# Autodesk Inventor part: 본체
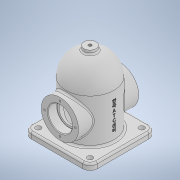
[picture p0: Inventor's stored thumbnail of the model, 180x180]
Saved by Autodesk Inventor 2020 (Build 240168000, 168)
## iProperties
Created: 2021-07
Part Number: 본체
Material: 일반
Document SubType Name: Modeling
Designer: Owner
Density: 1 g/cm^3
Appearance: 기본값
Mass: 320.706 g
Surface Area: 800.755 cm^2
Volume: 320.706 cm^3
Author: Owner
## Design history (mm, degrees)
sketch "스케치1"
  geometry: C1 r 40 at (0, 0); 1 further point
  constraints: 1 centre point, 1 coincident
  dimensions: "d0" = 80 diameter of C1
extrude "돌출1" new body sketch "스케치1" distance "d1" = 124; taper "d2" = 0 deg
fillet "모깎기1" dims "d3" = 40
feature "쉘1" dims "d4" = 8
node "작업 평면1"
sketch "스케치2"
  geometry: C1 r 31 at (0, 48); 1 further point
  constraints: 1 centre point, 1 vertical alignment
  dimensions: "d6" = 62 diameter of C1; "d7" = 48 distance of point (0, 0) C1.centre
extrude "돌출2" join sketch "스케치2" stored distance "d8" = 124; taper "d9" = 0 deg
sketch "스케치3" dims "d10" = 51
  geometry: 3 further points
  constraints: 2 vertical alignment, 2 other
  dimensions: "d11" = 48 distance of point (0, -48) point (0, 0)
hole "구멍1" sketch "스케치3" at (0, 25.5) diameter "d12" = 3.242; stored, may be unused: countersink angle "d16" = 90 deg, drill point angle "d18" = 118 deg; dims "d13" = 8, "d14" = 4, "d15" = 2, "d17" = 10
sketch "스케치4"
  geometry: C1 r 31 at (0, 0) reference; 2 further points
  constraints: 1 coincident
hole "구멍2" sketch "스케치4" at (0, 0) diameter "d22" = 33; stored, may be unused: countersink angle "d26" = 90 deg, drill point angle "d28" = 118 deg; dims "d23" = 8, "d24" = 40, "d25" = 15, "d27" = 10
chamfer "모따기1" distance "d29" = 1; stored, may be unused: second distance "d30" = 2, angle "d31" = 45 deg
fillet "모깎기2" dims "d32" = 0.3
fillet "모깎기3" dims "d33" = 3
node "작업 평면2"
sketch "스케치5"
  geometry: 2 further points
  constraints: 1 horizontal alignment, 1 other
  dimensions: "d35" = 48 distance of point (0, 0) point (48, 0)
feature "엠보싱1" sketch "스케치5" dims "d36" = 0.5, "d37" = 0
node "작업 평면3"
sketch "스케치6"
  geometry: C1 r 10 at (0, 0); 1 further point
  constraints: 1 centre point, 1 coincident
  dimensions: "d39" = 20 diameter of C1
extrude "돌출3" join sketch "스케치6" stored distance "d40" = 124; taper "d41" = 0 deg
sketch "스케치7"
  geometry: C1 r 10 at (0, 0) reference; 2 further points
  constraints: 1 coincident
hole "구멍3" sketch "스케치7" at (0, 0) diameter "d42" = 5.1881; stored, may be unused: countersink angle "d46" = 90 deg, drill point angle "d48" = 118 deg; dims "d43" = 15, "d44" = 4, "d45" = 2, "d47" = 16
fillet "모깎기4" dims "d49" = 3
sketch "스케치8"
  geometry: L1 (55, 55)-(-55, 55); L2 (-55, 55)-(-55, -55); L3 (-55, -55)-(55, -55); L4 (55, -55)-(55, 55); L5 (55, 55)-(-55, -55); L6 (-55, 55)-(55, -55); C1 r 32 at (0, 0) reference; C2 r 40 at (0, 0) reference; 1 further point
  constraints: 12 end point, 2 midpoint, 2 parallel, 1 horizontal, 1 perpendicular
  dimensions: "d50" = 110 distance of L3.end L2.end; "d51" = 110 distance of L2.end L1.end
extrude "돌출4" join sketch "스케치8" distance "d52" = 10; taper "d53" = 0 deg
fillet "모깎기5" dims "d54" = 12
fillet "모깎기6" dims "d55" = 3
sketch "스케치9"
  geometry: A1 r 9 centre (-43, -43) between (-52, -43) and (-43, -52) reference; 2 further points
  constraints: 1 coincident
hole "구멍4" sketch "스케치9" at (-43, -43) diameter "d56" = 9; stored, may be unused: countersink angle "d60" = 90 deg, drill point angle "d62" = 0 deg; dims "d57" = 15, "d58" = 4, "d59" = 2, "d61" = 10
fillet "모깎기7" dims "d66" = 3
node "솔리드1"
pattern_circular "원형 패턴1" dims angle "d20" = 360 deg
mirror "미러1"
pattern_circular "원형 패턴2" dims angle "d64" = 360 deg
feature "A9D066F2-1C7D-4E18-AEED-F7BC21143FA4" dims "d22" = 33, "d23" = 8, "d24" = 40, "d25" = 15, "d26" = 90 deg, "d27" = 10, "d28" = 118 deg
other parameters: "d38" = 129
